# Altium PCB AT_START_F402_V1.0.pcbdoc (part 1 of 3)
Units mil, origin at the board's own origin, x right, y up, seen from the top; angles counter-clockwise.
Board outline 15424.54 x 3536.36 mil, 2 copper layers (Top Layer, Bottom Layer); 138 components, 133 nets, 522 pads, 730 vias.
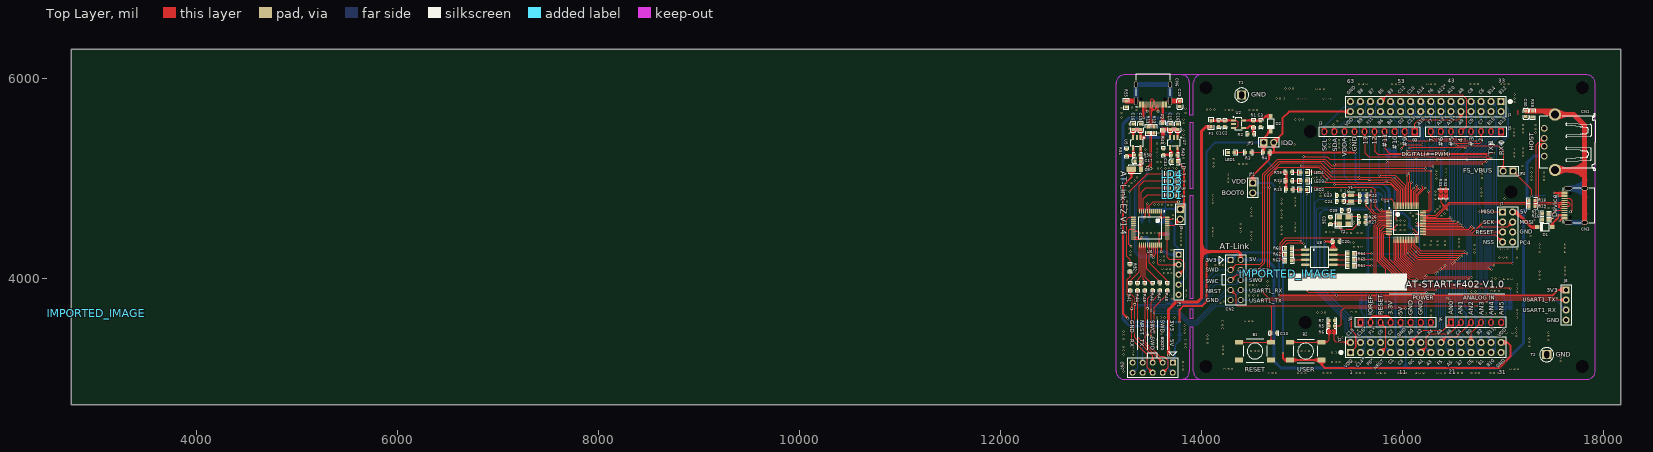
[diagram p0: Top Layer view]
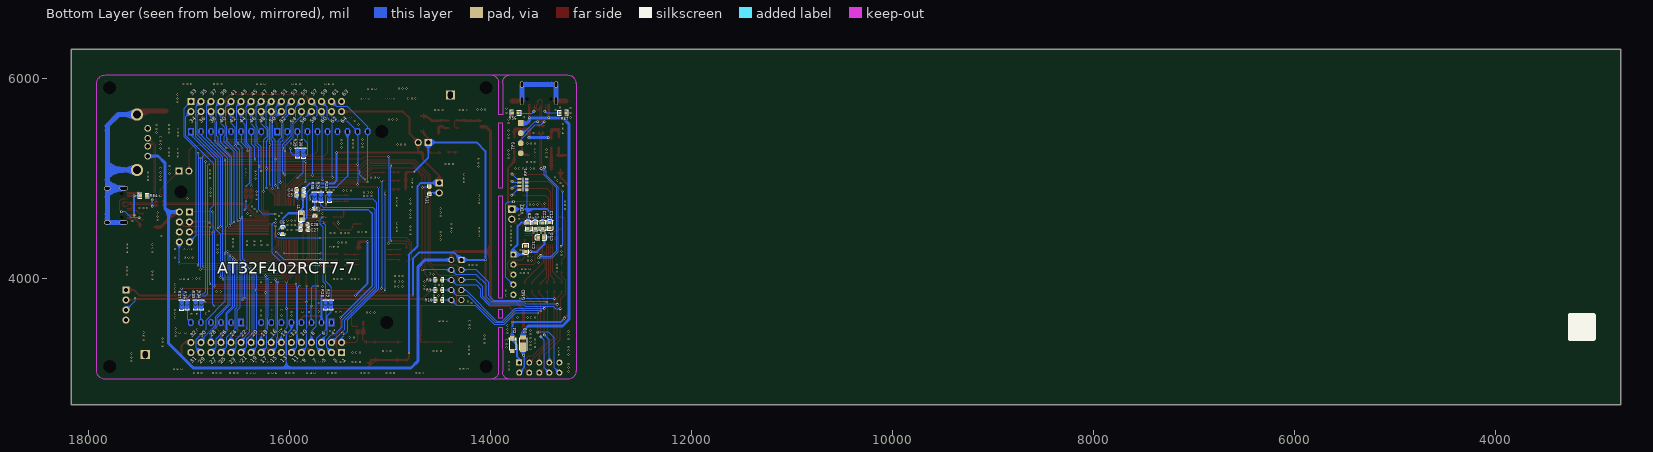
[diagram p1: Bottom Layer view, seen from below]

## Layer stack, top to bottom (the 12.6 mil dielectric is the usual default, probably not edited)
Top Layer: signal copper (thickness not stored)
Dielectric: dielectric 12.6, FR-4, Dk 4.8
Bottom Layer: signal copper (thickness not stored)

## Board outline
18174.54,2750 2750,2750 2750,6286.36 18174.54,6286.36
cut-out: 17855.2,5903.56 ccw(c17792.21,5903.56) 17729.21,5903.56 ccw(c17792.21,5903.56)
cut-out: 17854.57,3128.57 ccw(c17791.58,3128.57) 17728.58,3128.57 ccw(c17791.58,3128.57)
cut-out: 14107.57,3128.57 ccw(c14044.58,3128.57) 13981.58,3128.57 ccw(c14044.58,3128.57)
cut-out: 14107.57,5903.56 ccw(c14044.58,5903.56) 13981.58,5903.56 ccw(c14044.58,5903.56)
cut-out: 17146.57,4866.56 ccw(c17083.58,4866.56) 17020.58,4866.56 ccw(c17083.58,4866.56)
cut-out: 15096.57,3566.57 ccw(c15033.58,3566.57) 14970.58,3566.57 ccw(c15033.58,3566.57)
cut-out: 15146.57,5466.56 ccw(c15083.58,5466.56) 15020.58,5466.56 ccw(c15083.58,5466.56)

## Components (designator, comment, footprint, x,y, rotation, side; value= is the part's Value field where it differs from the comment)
B1 "BUTTON_SMT,6.0x6.0x4.5mm" BUTTON_SMT_6*6*5 14533.58,3281.57 r0 top
B2 "BUTTON_SMT,6.0x6.0x4.5mm" BUTTON_SMT_6*6*5 15038.58,3281.57 r180 top
C1 "10uF" 0603_C-M 14172.58,5545.37 r90 top
C2 "0.1uF" 0603_C-M 14232.58,5545.37 r90 top
C3 "10uF" 0603_C-M 14590.58,5545.37 r90 top
C4 "4.7uF" 0603_C-M 15896.58,4884.56 r180 bottom
C5 "0.1uF" 0603_C-M 15897.08,4834.56 r180 bottom
C6 "0.1uF" 0603_C-M 16069.58,4481.56 r90 bottom
C7 "0.1uF" 0603_C-M 15750.58,4663.56 r90 bottom
C8 "4.7uF" C0603 13556.58,4528.56 r270 bottom
C9 "CC0603KRX7R9BB104" C0603 13628.58,4528.56 r270 bottom
C10 "CC0603KRX7R9BB104" C0603 13498.58,4412.56 r0 bottom
C11 "CC0603KRX7R9BB104" C0603 13650.58,4300.56 r90 bottom
C12 "CC0603KRX7R9BB104" C0603 13410.58,4534.56 r270 bottom
C13 "0.1uF" 0603_C-M 14720.58,3460.57 r0 top
C14 "CL10A106KP8NNNC" C0603 13736.58,5165.56 r180 top
C15 "CL10A106KP8NNNC" C0603 13689.58,5515.56 r90 top
C16 "CC0603KRX7R9BB104" C0603 13764.58,5515.12 r90 top
C17 "CL10A106KP8NNNC" C0603 13367.58,5173.56 r180 top
C18 "CL10A106KP8NNNC" C0603 13319.58,5514.56 r90 top
C19 "CC0603KRX7R9BB104" C0603 13395.58,5514.12 r90 top
C20 "0.1uF" 0603_C-M 15341.08,4371.56 r0 top
C22 "CC0603KRX7R9BB104" C0603 13480.58,4530.56 r270 bottom
C23 "18pF" 0603_C-M 15383.58,4832.56 r180 top
C24 "18pF" 0603_C-M 15383.58,4773.56 r180 top
C25 "15pF" 0603_C-M 15433.08,4684.56 r180 top
C26 "15pF" 0603_C-M 15283.58,4577.06 r90 top
C27 "1uF" 0603_C-M 15857.08,4488.56 r180 bottom
C28 "0.1uF" 0603_C-M 15857.08,4537.56 r180 bottom
C29 "CC0603KRX7R9BB104" C0603 13784.58,5743.56 r90 top
C30 "CC0603KRX7R9BB104" C0603 17229.58,5643.01 r90 top
CN1 "USB type A" USB-A-TH__USB-AF-90 17466.58,5360.56 r90 top
CN2 "NC(Header 2x5)" HDR2X5#1 14290.92,4189.85 r270 top
CN3 "TYPEC-304-BCP16" USB-C-SMD_TYPEC-304-BCP16#1 17715.58,4731.56 r90 top
CN6 "TYPEC-304-BCP16" USB-C-SMD_TYPEC-304-BCP16#2 13518.58,5835.56 r180 top
CN7 "CON1" HDR2X5#2 13715.38,3166.97 r180 top
D1 "DFLS130L-7" SOD-123 17417.58,4515.56 r0 top
D2 "DFLS130L-7" SOD-123 14690.58,5545.36 r90 top
D3 "DFLS130L-7" POWERDI-123_L2.8-W1.8-LS3.7-RD 13676.62,3368.57 r90 bottom
D4 "SMF3.3A" SOD-123_L2.8-W1.8-LS3.7-RD 13782.58,3348.57 r270 bottom
D5 "DFLS130L-7" POWERDI-123_L2.8-W1.8-LS3.7-RD 13350.58,5091.56 r0 top
F1 "SMD0603B050TF" R0603#1 14096.58,5514.86 r90 top
F2 "SMD0603B050TF" R0603#2 13616.58,5518.56 r270 top
IMPORTED_IMAGE "IMPORTED_IMAGE" IMPORTED_IMAGE 3000,3659.57 r0 top
IMPORTED_IMAGE "IMPORTED_IMAGE" IMPORTED_IMAGE 14864.58,4052.57 r0 top
J1 "Header 2x16" HDR-M-2.54_2X16 16233.44,5715.86 r180 top
J2 "Header 2x16" HDR-M-2.54_2X16 16233.88,3318.14 r0 top
J3 "CON10" "FEMALE HEADER 1X10" 16123.87,5466.56 r180 top
J4 "CON8" "FEMALE HEADER 1X8" 15583.87,3566.56 r0 top
J5 "CON8" "FEMALE HEADER 1X8" 16983.87,5466.56 r180 top
J6 "CON6" "FEMALE HEADER 1X6" 16483.87,3566.57 r0 top
J7 "Header 4X2" HDR2X4 16998.88,4667.16 r270 top
J8 "Header 1x4" HDR1X4 17630.74,3890.57 r270 top
J9 "1X2P,Male,DIP_2.54" HDR1X2 13789.38,4693.97 r270 top
JP1 "NC(Header 1x2)" "HEADER 1X2" 14511.58,4956.56 r270 top
JP2 "NC(Header 1x2)" "HEADER 1X2" 17103.58,5073.56 r180 top
JP3 "NC(Header 1x2)" "HEADER 1X2" 14620.58,5358.56 r0 top
L1 "0.5A,600R@100Mhz" 0603_L 15884.58,4623.56 r270 bottom
LD1 "RED" LED0603 13742.58,4833.77 r180 top
LD2 "GREEN" LED0603 13742.58,4903.37 r180 top
LD3 "BLUE" LED0603 13742.58,4972.97 r180 top
LD4 "YELLOW" LED0603 13742.58,5042.56 r180 top
LED1 "RED" LED0603 14328.58,5259.56 r180 top
LED2 "RED" LED0603 14988.58,4890.56 r0 top
LED3 "YELLOW" LED0603 14988.58,4976.56 r0 top
LED4 "GREEN" LED0603 14988.58,5060.56 r0 top
P1 "HDR-M-2.54_1x5" HDR-M-2.54_1X5 13772.58,4042.57 r270 top
R1 "51k" 0603_R-M 14518.58,5545.37 r270 top
R2 "15k" 0603_R-M 14490.58,5444.56 r180 top
R3 "1K" 0603_R-M 14466.58,5259.56 r0 top
R4 "0R" 0603_R-M 14647.58,5258.56 r0 top
R5 "0R" 0603_R-M 15296.58,3530.57 r0 top
R6 "NC" SB-PAD 15296.58,3474.57 r0 top
R7 "100K" 0603_R-M 15296.58,3586.57 r180 top
R8 "470R" 0603_R-M 14518.27,3990.76 r0 bottom
R9 "470R" 0603_R-M 14518.27,3888.76 r0 bottom
R10 "470R" 0603_R-M 14518.27,3790.76 r0 bottom
R11 "0603WAF0000T5E" R0603#2 13469.58,5485.9 r270 top
R12 "0603WAF0000T5E" R0603#2 13528.58,5485.56 r270 top
R13 "1K" 0603_R-M 14872.58,4890.56 r0 top
R14 "1K" 0603_R-M 14871.19,4976.21 r0 top
R15 "1K" 0603_R-M 14871.19,5062.21 r0 top
R16 "0603WAF5101T5E" R0603#2 17423.58,4589.56 r180 top
R17 "0603WAF5101T5E" R0603#2 17422.58,4649.56 r180 top
R18 "0603WAF220JT5E" R0603#2 17291.92,4780.56 r0 top
R19 "0603WAF220JT5E" R0603#2 17291.58,4721.56 r0 top
R22 "0R" 0603_R-M 15609.58,4832.56 r0 top
R23 "0R" 0603_R-M 15611.58,4774.56 r0 top
R24 "NC" SB-PAD 15689.58,4815.56 r270 bottom
R25 "NC" SB-PAD 15605.58,4815.56 r270 bottom
R26 "0R" 0603_R-M 15600.58,4616.56 r0 top
R27 "0R" 0603_R-M 15600.58,4562.56 r0 top
R28 "NC" SB-PAD 15643.58,3742.57 r270 bottom
R29 "NC" SB-PAD 15589.58,3743.57 r270 bottom
R31 "10K" 0603_R-M 14610.58,4883.56 r270 bottom
R32 "NC" SB-PAD 16433.58,4848.44 r270 top
R33 "NC" SB-PAD 16380.58,4848.85 r270 top
R34 "0R" SB-PAD 16880.58,3742.45 r270 bottom
R35 "NC" SB-PAD 16936.58,3741.96 r270 bottom
R36 "NC" SB-PAD 17020.58,3741.45 r270 bottom
R37 "0R" SB-PAD 17076.58,3740.84 r270 bottom
R38 "NC" SB-PAD 15864.58,5253.93 r270 bottom
R39 "0R" SB-PAD 15924.58,5254.56 r270 bottom
R41 "33R" 0603_R-M 13290.58,3920.57 r270 top
R43 "47K" 0603_R-M 13730.42,5236.02 r180 top
R44 "33R" 0603_R-M 13364.58,3920.57 r270 top
R45 "33R" 0603_R-M 13436.58,3920.57 r270 top
R46 "33R" 0603_R-M 13514.58,3922.57 r270 top
R47 "33R" 0603_R-M 13586.58,3924.57 r270 top
R48 "33R" 0603_R-M 13660.58,3920.57 r270 top
R49 "15K" 0603_R-M 13620.58,5264.56 r270 top
R50 "51K" 0603_R-M 13362.58,5233.56 r180 top
R51 "15K" 0603_R-M 13254.58,5258.56 r270 top
R52 "33R" 0603_R-M 13288.58,4110.56 r270 top
R54 "0603WAF1002T5E" R0603#2 17455.92,4827.56 r0 bottom
R55 "RC0603FR-071ML" R0603#2 13250.58,5741.9 r270 top
R56 "0603WAF5101T5E" R0603#2 13755.58,5651.56 r0 bottom
R57 "0603WAF5101T5E" R0603#2 13279.58,5651.56 r180 bottom
R58 "0R" SB-PAD 15750.58,4817.56 r270 bottom
R59 "RC0603FR-071ML" R0603#2 17296.58,5641.9 r270 top
R60 "0603WAF330JT5E" R0603#2 14866.58,4300.56 r0 top
R61 "0603WAF330JT5E" R0603#2 15486.24,4131.56 r180 top
R62 "0603WAF330JT5E" R0603#2 14866.92,4241.56 r0 top
R63 "0603WAF330JT5E" R0603#2 14867.58,4181.56 r0 top
R64 "0603WAF330JT5E" R0603#2 15486.92,4251.56 r180 top
R65 "0603WAF330JT5E" R0603#2 15486.92,4191.56 r180 top
RP1 "1K" 0603*4,8P4R 13640.58,4887.56 r90 bottom
T1 "Testpoint" TESTHOOK 14400.58,5830.56 r270 top
T2 "Testpoint" TESTHOOK 17437.58,3246.57 r90 top
TP3 "1X4P_2.54F" "HDR1X4 - TOP" 13699.93,5551.02 r90 bottom
U2 "RT9080N-08GJ5" SOT-23-5 14382.58,5477.54 r0 top
U4 "AT32F402RCT7-7" IC_LQFP64_7X7 16037.58,4559.56 r0 top
U5 "RT9080N-08GJ5" SOT-23-5 13295.14,5340.91 r270 top
U6 "AT32F403CGT6" "LQFP48 - 2" 13600.09,4673.02 r270 top
U7 "RT9080N-08GJ5" SOT-23-5 13664.35,5342.91 r270 top
U8 "EN25QH128A-104HIP2T" SOP-8_L5.3-W5.3-P1.27-LS8.0-BL 15174.58,4216.56 r270 top
Y1 "32.768KHz" "XTAL_SOP - FC-12M" 15487.58,4832.56 r270 top
Y2 "CJ13-120001210B20" CRYSTAL-SMD_4P-L3.2-W2.5-BL 15416.58,4583.56 r0 top

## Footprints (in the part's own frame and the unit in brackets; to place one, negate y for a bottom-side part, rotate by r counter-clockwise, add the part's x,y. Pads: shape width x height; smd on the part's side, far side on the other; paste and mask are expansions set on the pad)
0603*4,8P4R [mm]
  rect 0.55x0.95 smd paste+0 mask+0.102: 1(0,0) 4(2.7,0) 5(2.7,1.85) 8(0,1.85)
  rect 0.5x0.95 smd paste+0 mask+0.102: 2(0.9,0) 3(1.8,0) 6(1.8,1.85) 7(0.9,1.85)
  silkscreen extent -0.43,0.94 3.1,0.94
0603_C-M [mil]
  rect 30x30 smd paste+0 mask+4: 1(27.5,0) 2(-27.5,0)
  silkscreen extent -50,-21 50,21
0603_L [mm]
  rect 0.93x0.9 smd paste+0 mask+0.102: 1(-0.77,0) 2(0.77,0)
  silkscreen extent -1.4,-0.64 1.4,0.64
0603_R-M [mil]
  rect 30x30 smd paste+0 mask+4: 1(27.5,0) 2(-27.5,0)
  silkscreen extent -50,-21 50,21
BUTTON_SMT_6*6*5 [mm]
  rect 2x1.2 smd paste+0 mask+0.102: 1(-4,2.25) 2(4,2.25) 3(-4,-2.25) 4(4,-2.25)
  silkscreen extent -3,-3 3,3
C0603 [mm]
  rect 0.8x0.9 smd paste+0 mask+0.051: 1(-0.7,0) 2(0.7,0)
  silkscreen extent -1.41,-0.71 1.39,0.72
CRYSTAL-SMD_4P-L3.2-W2.5-BL [mm]
  rect 1.4x1.2 smd paste+0 mask+0.051: 1(-1.1,-0.85) 2(1.1,-0.85) 3(1.1,0.85) 4(-1.1,0.85)
  silkscreen extent -2.26,-1.91 2.03,1.68
"FEMALE HEADER 1X6" [mm]
  oval 1x0.7 hole 0.7 slot 1 at 90 deg: 1(0,0) 2(2.54,0) 3(5.08,0) 4(7.62,0) 5(10.16,0) 6(12.7,0)
  Top Layer region: 13.4,-0.2 13.306,-0.55 13.05,-0.806 12.7,-0.9 12.35,-0.806 12.094,-0.55 12,-0.2 12,0.2 12.094,0.55 12.35,0.806 12.7,0.9 13.05,0.806 13.306,0.55 13.4,0.2
  Top Layer region: 10.86,-0.2 10.766,-0.55 10.51,-0.806 10.16,-0.9 9.81,-0.806 9.554,-0.55 9.46,-0.2 9.46,0.2 9.554,0.55 9.81,0.806 10.16,0.9 10.51,0.806 10.766,0.55 10.86,0.2
  Top Layer region: 8.32,-0.2 8.226,-0.55 7.97,-0.806 7.62,-0.9 7.27,-0.806 7.014,-0.55 6.92,-0.2 6.92,0.2 7.014,0.55 7.27,0.806 7.62,0.9 7.97,0.806 8.226,0.55 8.32,0.2
  Top Layer region: 5.78,-0.2 5.686,-0.55 5.43,-0.806 5.08,-0.9 4.73,-0.806 4.474,-0.55 4.38,-0.2 4.38,0.2 4.474,0.55 4.73,0.806 5.08,0.9 5.43,0.806 5.686,0.55 5.78,0.2
  Top Layer region: 3.24,-0.2 3.146,-0.55 2.89,-0.806 2.54,-0.9 2.19,-0.806 1.934,-0.55 1.84,-0.2 1.84,0.2 1.934,0.55 2.19,0.806 2.54,0.9 2.89,0.806 3.146,0.55 3.24,0.2
  Top Layer region: -0.7,0.9 0.7,0.9 0.7,-0.9 -0.7,-0.9
  Bottom Layer region: 13.4,-0.2 13.306,-0.55 13.05,-0.806 12.7,-0.9 12.35,-0.806 12.094,-0.55 12,-0.2 12,0.2 12.094,0.55 12.35,0.806 12.7,0.9 13.05,0.806 13.306,0.55 13.4,0.2
  Bottom Layer region: 10.86,-0.2 10.766,-0.55 10.51,-0.806 10.16,-0.9 9.81,-0.806 9.554,-0.55 9.46,-0.2 9.46,0.2 9.554,0.55 9.81,0.806 10.16,0.9 10.51,0.806 10.766,0.55 10.86,0.2
  Bottom Layer region: 8.32,-0.2 8.226,-0.55 7.97,-0.806 7.62,-0.9 7.27,-0.806 7.014,-0.55 6.92,-0.2 6.92,0.2 7.014,0.55 7.27,0.806 7.62,0.9 7.97,0.806 8.226,0.55 8.32,0.2
  Bottom Layer region: 5.78,-0.2 5.686,-0.55 5.43,-0.806 5.08,-0.9 4.73,-0.806 4.474,-0.55 4.38,-0.2 4.38,0.2 4.474,0.55 4.73,0.806 5.08,0.9 5.43,0.806 5.686,0.55 5.78,0.2
  Bottom Layer region: 3.24,-0.2 3.146,-0.55 2.89,-0.806 2.54,-0.9 2.19,-0.806 1.934,-0.55 1.84,-0.2 1.84,0.2 1.934,0.55 2.19,0.806 2.54,0.9 2.89,0.806 3.146,0.55 3.24,0.2
  Bottom Layer region: -0.7,0.9 0.7,0.9 0.7,-0.9 -0.7,-0.9
  Multi-Layer region: 13.4,-0.2 13.306,-0.55 13.05,-0.806 12.7,-0.9 12.35,-0.806 12.094,-0.55 12,-0.2 12,0.2 12.094,0.55 12.35,0.806 12.7,0.9 13.05,0.806 13.306,0.55 13.4,0.2
  Multi-Layer region: 10.86,-0.2 10.766,-0.55 10.51,-0.806 10.16,-0.9 9.81,-0.806 9.554,-0.55 9.46,-0.2 9.46,0.2 9.554,0.55 9.81,0.806 10.16,0.9 10.51,0.806 10.766,0.55 10.86,0.2
  Multi-Layer region: 8.32,-0.2 8.226,-0.55 7.97,-0.806 7.62,-0.9 7.27,-0.806 7.014,-0.55 6.92,-0.2 6.92,0.2 7.014,0.55 7.27,0.806 7.62,0.9 7.97,0.806 8.226,0.55 8.32,0.2
  Multi-Layer region: 5.78,-0.2 5.686,-0.55 5.43,-0.806 5.08,-0.9 4.73,-0.806 4.474,-0.55 4.38,-0.2 4.38,0.2 4.474,0.55 4.73,0.806 5.08,0.9 5.43,0.806 5.686,0.55 5.78,0.2
  Multi-Layer region: 3.24,-0.2 3.146,-0.55 2.89,-0.806 2.54,-0.9 2.19,-0.806 1.934,-0.55 1.84,-0.2 1.84,0.2 1.934,0.55 2.19,0.806 2.54,0.9 2.89,0.806 3.146,0.55 3.24,0.2
  Multi-Layer region: -0.7,0.9 0.7,0.9 0.7,-0.9 -0.7,-0.9
  silkscreen extent -1.27,-1.17 13.97,1.27
"FEMALE HEADER 1X8" [mm]
  oval 1x0.7 hole 0.7 slot 1 at 90 deg: 1(0,0) 2(2.54,0) 3(5.08,0) 4(7.62,0) 5(10.16,0) 6(12.7,0) 7(15.24,0) 8(17.78,0)
  Top Layer region: -0.7,0.9 0.7,0.9 0.7,-0.9 -0.7,-0.9
  Top Layer region: 3.24,-0.2 3.146,-0.55 2.89,-0.806 2.54,-0.9 2.19,-0.806 1.934,-0.55 1.84,-0.2 1.84,0.2 1.934,0.55 2.19,0.806 2.54,0.9 2.89,0.806 3.146,0.55 3.24,0.2
  Top Layer region: 5.78,-0.2 5.686,-0.55 5.43,-0.806 5.08,-0.9 4.73,-0.806 4.474,-0.55 4.38,-0.2 4.38,0.2 4.474,0.55 4.73,0.806 5.08,0.9 5.43,0.806 5.686,0.55 5.78,0.2
  Top Layer region: 8.32,-0.2 8.226,-0.55 7.97,-0.806 7.62,-0.9 7.27,-0.806 7.014,-0.55 6.92,-0.2 6.92,0.2 7.014,0.55 7.27,0.806 7.62,0.9 7.97,0.806 8.226,0.55 8.32,0.2
  Top Layer region: 10.86,-0.2 10.766,-0.55 10.51,-0.806 10.16,-0.9 9.81,-0.806 9.554,-0.55 9.46,-0.2 9.46,0.2 9.554,0.55 9.81,0.806 10.16,0.9 10.51,0.806 10.766,0.55 10.86,0.2
  Top Layer region: 13.4,-0.2 13.306,-0.55 13.05,-0.806 12.7,-0.9 12.35,-0.806 12.094,-0.55 12,-0.2 12,0.2 12.094,0.55 12.35,0.806 12.7,0.9 13.05,0.806 13.306,0.55 13.4,0.2
  Top Layer region: 15.94,-0.2 15.846,-0.55 15.59,-0.806 15.24,-0.9 14.89,-0.806 14.634,-0.55 14.54,-0.2 14.54,0.2 14.634,0.55 14.89,0.806 15.24,0.9 15.59,0.806 15.846,0.55 15.94,0.2
  Top Layer region: 18.48,-0.2 18.386,-0.55 18.13,-0.806 17.78,-0.9 17.43,-0.806 17.174,-0.55 17.08,-0.2 17.08,0.2 17.174,0.55 17.43,0.806 17.78,0.9 18.13,0.806 18.386,0.55 18.48,0.2
  Bottom Layer region: -0.7,0.9 0.7,0.9 0.7,-0.9 -0.7,-0.9
  Bottom Layer region: 3.24,-0.2 3.146,-0.55 2.89,-0.806 2.54,-0.9 2.19,-0.806 1.934,-0.55 1.84,-0.2 1.84,0.2 1.934,0.55 2.19,0.806 2.54,0.9 2.89,0.806 3.146,0.55 3.24,0.2
  Bottom Layer region: 5.78,-0.2 5.686,-0.55 5.43,-0.806 5.08,-0.9 4.73,-0.806 4.474,-0.55 4.38,-0.2 4.38,0.2 4.474,0.55 4.73,0.806 5.08,0.9 5.43,0.806 5.686,0.55 5.78,0.2
  Bottom Layer region: 8.32,-0.2 8.226,-0.55 7.97,-0.806 7.62,-0.9 7.27,-0.806 7.014,-0.55 6.92,-0.2 6.92,0.2 7.014,0.55 7.27,0.806 7.62,0.9 7.97,0.806 8.226,0.55 8.32,0.2
  Bottom Layer region: 10.86,-0.2 10.766,-0.55 10.51,-0.806 10.16,-0.9 9.81,-0.806 9.554,-0.55 9.46,-0.2 9.46,0.2 9.554,0.55 9.81,0.806 10.16,0.9 10.51,0.806 10.766,0.55 10.86,0.2
  Bottom Layer region: 13.4,-0.2 13.306,-0.55 13.05,-0.806 12.7,-0.9 12.35,-0.806 12.094,-0.55 12,-0.2 12,0.2 12.094,0.55 12.35,0.806 12.7,0.9 13.05,0.806 13.306,0.55 13.4,0.2
  Bottom Layer region: 15.94,-0.2 15.846,-0.55 15.59,-0.806 15.24,-0.9 14.89,-0.806 14.634,-0.55 14.54,-0.2 14.54,0.2 14.634,0.55 14.89,0.806 15.24,0.9 15.59,0.806 15.846,0.55 15.94,0.2
  Bottom Layer region: 18.48,-0.2 18.386,-0.55 18.13,-0.806 17.78,-0.9 17.43,-0.806 17.174,-0.55 17.08,-0.2 17.08,0.2 17.174,0.55 17.43,0.806 17.78,0.9 18.13,0.806 18.386,0.55 18.48,0.2
  Multi-Layer region: -0.7,0.9 0.7,0.9 0.7,-0.9 -0.7,-0.9
  Multi-Layer region: 3.24,-0.2 3.146,-0.55 2.89,-0.806 2.54,-0.9 2.19,-0.806 1.934,-0.55 1.84,-0.2 1.84,0.2 1.934,0.55 2.19,0.806 2.54,0.9 2.89,0.806 3.146,0.55 3.24,0.2
  Multi-Layer region: 5.78,-0.2 5.686,-0.55 5.43,-0.806 5.08,-0.9 4.73,-0.806 4.474,-0.55 4.38,-0.2 4.38,0.2 4.474,0.55 4.73,0.806 5.08,0.9 5.43,0.806 5.686,0.55 5.78,0.2
  Multi-Layer region: 8.32,-0.2 8.226,-0.55 7.97,-0.806 7.62,-0.9 7.27,-0.806 7.014,-0.55 6.92,-0.2 6.92,0.2 7.014,0.55 7.27,0.806 7.62,0.9 7.97,0.806 8.226,0.55 8.32,0.2
  Multi-Layer region: 10.86,-0.2 10.766,-0.55 10.51,-0.806 10.16,-0.9 9.81,-0.806 9.554,-0.55 9.46,-0.2 9.46,0.2 9.554,0.55 9.81,0.806 10.16,0.9 10.51,0.806 10.766,0.55 10.86,0.2
  Multi-Layer region: 13.4,-0.2 13.306,-0.55 13.05,-0.806 12.7,-0.9 12.35,-0.806 12.094,-0.55 12,-0.2 12,0.2 12.094,0.55 12.35,0.806 12.7,0.9 13.05,0.806 13.306,0.55 13.4,0.2
  Multi-Layer region: 15.94,-0.2 15.846,-0.55 15.59,-0.806 15.24,-0.9 14.89,-0.806 14.634,-0.55 14.54,-0.2 14.54,0.2 14.634,0.55 14.89,0.806 15.24,0.9 15.59,0.806 15.846,0.55 15.94,0.2
  Multi-Layer region: 18.48,-0.2 18.386,-0.55 18.13,-0.806 17.78,-0.9 17.43,-0.806 17.174,-0.55 17.08,-0.2 17.08,0.2 17.174,0.55 17.43,0.806 17.78,0.9 18.13,0.806 18.386,0.55 18.48,0.2
  silkscreen extent -1.27,-1.17 19.05,1.27
"FEMALE HEADER 1X10" [mm]
  oval 1x0.7 hole 0.7 slot 1 at 90 deg: 1(0,0) 2(2.54,0) 3(5.08,0) 4(7.62,0) 5(10.16,0) 6(12.7,0) 7(15.24,0) 8(17.78,0) 9(20.32,0) 10(22.86,0)
  Top Layer region: 23.56,-0.2 23.466,-0.55 23.21,-0.806 22.86,-0.9 22.51,-0.806 22.254,-0.55 22.16,-0.2 22.16,0.2 22.254,0.55 22.51,0.806 22.86,0.9 23.21,0.806 23.466,0.55 23.56,0.2
  Top Layer region: 21.02,-0.2 20.926,-0.55 20.67,-0.806 20.32,-0.9 19.97,-0.806 19.714,-0.55 19.62,-0.2 19.62,0.2 19.714,0.55 19.97,0.806 20.32,0.9 20.67,0.806 20.926,0.55 21.02,0.2
  Top Layer region: 18.48,-0.2 18.386,-0.55 18.13,-0.806 17.78,-0.9 17.43,-0.806 17.174,-0.55 17.08,-0.2 17.08,0.2 17.174,0.55 17.43,0.806 17.78,0.9 18.13,0.806 18.386,0.55 18.48,0.2
  Top Layer region: 15.94,-0.2 15.846,-0.55 15.59,-0.806 15.24,-0.9 14.89,-0.806 14.634,-0.55 14.54,-0.2 14.54,0.2 14.634,0.55 14.89,0.806 15.24,0.9 15.59,0.806 15.846,0.55 15.94,0.2
  Top Layer region: 13.4,-0.2 13.306,-0.55 13.05,-0.806 12.7,-0.9 12.35,-0.806 12.094,-0.55 12,-0.2 12,0.2 12.094,0.55 12.35,0.806 12.7,0.9 13.05,0.806 13.306,0.55 13.4,0.2
  Top Layer region: 10.86,-0.2 10.766,-0.55 10.51,-0.806 10.16,-0.9 9.81,-0.806 9.554,-0.55 9.46,-0.2 9.46,0.2 9.554,0.55 9.81,0.806 10.16,0.9 10.51,0.806 10.766,0.55 10.86,0.2
  Top Layer region: 8.32,-0.2 8.226,-0.55 7.97,-0.806 7.62,-0.9 7.27,-0.806 7.014,-0.55 6.92,-0.2 6.92,0.2 7.014,0.55 7.27,0.806 7.62,0.9 7.97,0.806 8.226,0.55 8.32,0.2
  Top Layer region: 5.78,-0.2 5.686,-0.55 5.43,-0.806 5.08,-0.9 4.73,-0.806 4.474,-0.55 4.38,-0.2 4.38,0.2 4.474,0.55 4.73,0.806 5.08,0.9 5.43,0.806 5.686,0.55 5.78,0.2
  Top Layer region: 3.24,-0.2 3.146,-0.55 2.89,-0.806 2.54,-0.9 2.19,-0.806 1.934,-0.55 1.84,-0.2 1.84,0.2 1.934,0.55 2.19,0.806 2.54,0.9 2.89,0.806 3.146,0.55 3.24,0.2
  Top Layer region: -0.7,0.9 0.7,0.9 0.7,-0.9 -0.7,-0.9
  Bottom Layer region: 23.56,-0.2 23.466,-0.55 23.21,-0.806 22.86,-0.9 22.51,-0.806 22.254,-0.55 22.16,-0.2 22.16,0.2 22.254,0.55 22.51,0.806 22.86,0.9 23.21,0.806 23.466,0.55 23.56,0.2
  Bottom Layer region: 21.02,-0.2 20.926,-0.55 20.67,-0.806 20.32,-0.9 19.97,-0.806 19.714,-0.55 19.62,-0.2 19.62,0.2 19.714,0.55 19.97,0.806 20.32,0.9 20.67,0.806 20.926,0.55 21.02,0.2
  Bottom Layer region: 18.48,-0.2 18.386,-0.55 18.13,-0.806 17.78,-0.9 17.43,-0.806 17.174,-0.55 17.08,-0.2 17.08,0.2 17.174,0.55 17.43,0.806 17.78,0.9 18.13,0.806 18.386,0.55 18.48,0.2
  Bottom Layer region: 15.94,-0.2 15.846,-0.55 15.59,-0.806 15.24,-0.9 14.89,-0.806 14.634,-0.55 14.54,-0.2 14.54,0.2 14.634,0.55 14.89,0.806 15.24,0.9 15.59,0.806 15.846,0.55 15.94,0.2
  Bottom Layer region: 13.4,-0.2 13.306,-0.55 13.05,-0.806 12.7,-0.9 12.35,-0.806 12.094,-0.55 12,-0.2 12,0.2 12.094,0.55 12.35,0.806 12.7,0.9 13.05,0.806 13.306,0.55 13.4,0.2
  Bottom Layer region: 10.86,-0.2 10.766,-0.55 10.51,-0.806 10.16,-0.9 9.81,-0.806 9.554,-0.55 9.46,-0.2 9.46,0.2 9.554,0.55 9.81,0.806 10.16,0.9 10.51,0.806 10.766,0.55 10.86,0.2
  Bottom Layer region: 8.32,-0.2 8.226,-0.55 7.97,-0.806 7.62,-0.9 7.27,-0.806 7.014,-0.55 6.92,-0.2 6.92,0.2 7.014,0.55 7.27,0.806 7.62,0.9 7.97,0.806 8.226,0.55 8.32,0.2
  Bottom Layer region: 5.78,-0.2 5.686,-0.55 5.43,-0.806 5.08,-0.9 4.73,-0.806 4.474,-0.55 4.38,-0.2 4.38,0.2 4.474,0.55 4.73,0.806 5.08,0.9 5.43,0.806 5.686,0.55 5.78,0.2
  Bottom Layer region: 3.24,-0.2 3.146,-0.55 2.89,-0.806 2.54,-0.9 2.19,-0.806 1.934,-0.55 1.84,-0.2 1.84,0.2 1.934,0.55 2.19,0.806 2.54,0.9 2.89,0.806 3.146,0.55 3.24,0.2
  Bottom Layer region: -0.7,0.9 0.7,0.9 0.7,-0.9 -0.7,-0.9
  Multi-Layer region: 23.56,-0.2 23.466,-0.55 23.21,-0.806 22.86,-0.9 22.51,-0.806 22.254,-0.55 22.16,-0.2 22.16,0.2 22.254,0.55 22.51,0.806 22.86,0.9 23.21,0.806 23.466,0.55 23.56,0.2
  Multi-Layer region: 21.02,-0.2 20.926,-0.55 20.67,-0.806 20.32,-0.9 19.97,-0.806 19.714,-0.55 19.62,-0.2 19.62,0.2 19.714,0.55 19.97,0.806 20.32,0.9 20.67,0.806 20.926,0.55 21.02,0.2
  Multi-Layer region: 18.48,-0.2 18.386,-0.55 18.13,-0.806 17.78,-0.9 17.43,-0.806 17.174,-0.55 17.08,-0.2 17.08,0.2 17.174,0.55 17.43,0.806 17.78,0.9 18.13,0.806 18.386,0.55 18.48,0.2
  Multi-Layer region: 15.94,-0.2 15.846,-0.55 15.59,-0.806 15.24,-0.9 14.89,-0.806 14.634,-0.55 14.54,-0.2 14.54,0.2 14.634,0.55 14.89,0.806 15.24,0.9 15.59,0.806 15.846,0.55 15.94,0.2
  Multi-Layer region: 13.4,-0.2 13.306,-0.55 13.05,-0.806 12.7,-0.9 12.35,-0.806 12.094,-0.55 12,-0.2 12,0.2 12.094,0.55 12.35,0.806 12.7,0.9 13.05,0.806 13.306,0.55 13.4,0.2
  Multi-Layer region: 10.86,-0.2 10.766,-0.55 10.51,-0.806 10.16,-0.9 9.81,-0.806 9.554,-0.55 9.46,-0.2 9.46,0.2 9.554,0.55 9.81,0.806 10.16,0.9 10.51,0.806 10.766,0.55 10.86,0.2
  Multi-Layer region: 8.32,-0.2 8.226,-0.55 7.97,-0.806 7.62,-0.9 7.27,-0.806 7.014,-0.55 6.92,-0.2 6.92,0.2 7.014,0.55 7.27,0.806 7.62,0.9 7.97,0.806 8.226,0.55 8.32,0.2
  Multi-Layer region: 5.78,-0.2 5.686,-0.55 5.43,-0.806 5.08,-0.9 4.73,-0.806 4.474,-0.55 4.38,-0.2 4.38,0.2 4.474,0.55 4.73,0.806 5.08,0.9 5.43,0.806 5.686,0.55 5.78,0.2
  Multi-Layer region: 3.24,-0.2 3.146,-0.55 2.89,-0.806 2.54,-0.9 2.19,-0.806 1.934,-0.55 1.84,-0.2 1.84,0.2 1.934,0.55 2.19,0.806 2.54,0.9 2.89,0.806 3.146,0.55 3.24,0.2
  Multi-Layer region: -0.7,0.9 0.7,0.9 0.7,-0.9 -0.7,-0.9
  silkscreen extent -1.27,-1.17 24.1,1.27
HDR1X2 [mm]
  rect 1.8x1.8 hole 1 slot 1.005 at 0 deg paste+0 mask+0.051: 1(0,0)
  round 1.8 hole 1 slot 1.005 at 0 deg paste+0 mask+0.051: 2(2.54,0)
  silkscreen extent -1.27,-1.27 3.81,1.27
HDR1X4 [mm]
  rect 1.8x1.8 hole 1 paste+0 mask+0.102: 1(0,0)
  round 1.8 hole 1 paste+0 mask+0.102: 2(2.54,0) 3(5.08,0) 4(7.62,0)
  silkscreen extent -1.27,-1.27 8.89,1.27
"HDR1X4 - TOP" [mm]
  rect 1.5x1.5 smd paste+0 mask+0.102: 1(0,0)
  round 1.5 smd paste+0 mask+0.102: 2(-2.54,0) 3(-5.08,0) 4(-7.62,0)
HDR2X4 [mm]
  rect 1.8x1.8 hole 1 paste+0 mask+0.102: 1(0,0)
  round 1.8 hole 1 paste+0 mask+0.102: 2(0,2.54) 3(2.54,0) 4(2.54,2.54) 5(5.08,0) 6(5.08,2.54) 7(7.62,0) 8(7.62,2.54)
  silkscreen extent -1.27,-1.27 8.89,3.81
HDR2X5#1 [mm]
  rect 1.5x1.5 hole 0.9 slot 0.905 at 0 deg paste+0 mask+0.051: 1(0,0)
  round 1.5 hole 0.9 slot 0.905 at 0 deg paste+0 mask+0.051: 2(0,2.54) 3(2.54,0) 4(2.54,2.54) 5(5.08,0) 6(5.08,2.54) 7(7.62,0) 8(7.62,2.54) 9(10.16,0) 10(10.16,2.54)
  silkscreen extent -1.27,-1.27 11.43,3.81
HDR2X5#2 [mm]
  rect 1.5x1.5 hole 0.9 paste+0 mask+0.102: 1(0,0)
  round 1.5 hole 0.9 paste+0 mask+0.102: 2(0,2.54) 3(2.54,0) 4(2.54,2.54) 5(5.08,0) 6(5.08,2.54) 7(7.62,0) 8(7.62,2.54) 9(10.16,0) 10(10.16,2.54)
  silkscreen extent -1.27,-1.27 11.43,3.81
HDR-M-2.54_1X5 [mil]
  rect 62x62 hole 35 paste+0 mask+2: 1(-200,0)
  round 62 hole 35 paste+0 mask+2: 2(-100,0) 3(0,0) 4(100,0) 5(200,0)
  silkscreen extent -250,-50 250,50
HDR-M-2.54_2X16 [mm]
  rect 1.8x1.8 hole 1 paste+0 mask+0.051: 1(-19.05,-1.27)
  round 1.8 hole 1 paste+0 mask+0.051: 2(-19.05,1.27) 3(-16.51,-1.27) 4(-16.51,1.27) 5(-13.97,-1.27) 6(-13.97,1.27) 7(-11.43,-1.27) 8(-11.43,1.27) 9(-8.89,-1.27) 10(-8.89,1.27) 11(-6.35,-1.27) 12(-6.35,1.27) 13(-3.81,-1.27) 14(-3.81,1.27) 15(-1.27,-1.27) 16(-1.27,1.27) 17(1.27,-1.27) 18(1.27,1.27) 19(3.81,-1.27) 20(3.81,1.27) 21(6.35,-1.27) 22(6.35,1.27) 23(8.89,-1.27) 24(8.89,1.27) 25(11.43,-1.27) 26(11.43,1.27) 27(13.97,-1.27) 28(13.97,1.27) 29(16.51,-1.27) 30(16.51,1.27) 31(19.05,-1.27) 32(19.05,1.27)
  silkscreen extent -20.32,-2.54 20.32,2.54
"HEADER 1X2" [mm]
  rect 1.8x1.8 hole 1 slot 1.005 at 0 deg paste+0 mask+0.051: 1(0,0)
  round 1.8 hole 1 slot 1.005 at 0 deg paste+0 mask+0.051: 2(2.54,0)
  silkscreen extent -1.27,-1.27 3.81,1.27
IC_LQFP64_7X7 [mm]
  rect 1.6x0.25 smd paste+0 mask+0.102: 1(-4.3,3) 2(-4.3,2.6) 3(-4.3,2.2) 4(-4.3,1.8) 5(-4.3,1.4) 6(-4.3,1) 7(-4.3,0.6) 8(-4.3,0.2) 9(-4.3,-0.2) 10(-4.3,-0.6) 11(-4.3,-1) 12(-4.3,-1.4) 13(-4.3,-1.8) 14(-4.3,-2.2) 15(-4.3,-2.6) 16(-4.3,-3) 33(4.3,-3) 34(4.3,-2.6) 35(4.3,-2.2) 36(4.3,-1.8) 37(4.3,-1.4) 38(4.3,-1) 39(4.3,-0.6) 40(4.3,-0.2) 41(4.3,0.2) 42(4.3,0.6) 43(4.3,1) 44(4.3,1.4) 45(4.3,1.8) 46(4.3,2.2) 47(4.3,2.6) 48(4.3,3)
  rect 0.25x1.6 smd paste+0 mask+0.102: 17(-3,-4.3) 18(-2.6,-4.3) 19(-2.2,-4.3) 20(-1.8,-4.3) 21(-1.4,-4.3) 22(-1,-4.3) 23(-0.6,-4.3) 24(-0.2,-4.3) 25(0.2,-4.3) 26(0.6,-4.3) 27(1,-4.3) 28(1.4,-4.3) 29(1.8,-4.3) 30(2.2,-4.3) 31(2.6,-4.3) 32(3,-4.3) 49(3,4.3) 50(2.6,4.3) 51(2.2,4.3) 52(1.8,4.3) 53(1.4,4.3) 54(1,4.3) 55(0.6,4.3) 56(0.2,4.3) 57(-0.2,4.3) 58(-0.6,4.3) 59(-1,4.3) 60(-1.4,4.3) 61(-1.8,4.3) 62(-2.2,4.3) 63(-2.6,4.3) 64(-3,4.3)
  silkscreen extent -4.42,-3.1 3.1,3.82
IMPORTED_IMAGE [mil]
LED0603 [mil]
  rect 36x32 smd paste+0 mask+4: 1(-0.04,0.2) 2(60.96,0.2)
  silkscreen extent -28,-28 110,27
"LQFP48 - 2" [mm]
  rect 1.2x0.3 smd paste+0 mask+0.102: 1(0,0) 2(0,-0.5) 3(0,-1) 4(0,-1.5) 5(0,-2) 6(0,-2.5) 7(0,-3) 8(0,-3.5) 9(0,-4) 10(0,-4.5) 11(0,-5) 12(0,-5.5) 25(8.5,-5.5) 26(8.5,-5) 27(8.5,-4.5) 28(8.5,-4) 29(8.5,-3.5) 30(8.5,-3) 31(8.5,-2.5) 32(8.5,-2) 33(8.5,-1.5) 34(8.5,-1) 35(8.5,-0.5) 36(8.5,0)
  rect 0.3x1.2 smd paste+0 mask+0.102: 13(1.5,-7) 14(2,-7) 15(2.5,-7) 16(3,-7) 17(3.5,-7) 18(4,-7) 19(4.5,-7) 20(5,-7) 21(5.5,-7) 22(6,-7) 23(6.5,-7) 24(7,-7) 37(7,1.5) 38(6.5,1.5) 39(6,1.5) 40(5.5,1.5) 41(5,1.5) 42(4.5,1.5) 43(4,1.5) 44(3.5,1.5) 45(3,1.5) 46(2.5,1.5) 47(2,1.5) 48(1.5,1.5)
  silkscreen extent -0.12,-5.71 7.11,0.89
POWERDI-123_L2.8-W1.8-LS3.7-RD [mm]
  rect 2.4x1.5 smd paste+0 mask+0.051: 1(-1.187,0)
  rect 1.05x1.5 smd paste+0 mask+0.051: 2(1.187,0)
  silkscreen extent -2,-1 1.2,1
R0603#1 [mil]
  rect 36x32 smd paste+0 mask+4: 1(-0.04,0.2) 2(60.96,0.2)
  silkscreen extent -28,-27 89,27
R0603#2 [mil]
  rect 31.75x34.02 smd paste-3937.01 mask+2: 1(-29.66,0) 2(29.66,0)
  silkscreen extent -55,-26 55,26
SB-PAD [mil]
  Top Layer region: -47.24,-19.68 -47.24,19.68 -16.45,19.68 1,0 -17.05,-19.68
  Top Layer region: -4.69,19.68 15,0 -4.69,-19.69 47.24,-19.68 47.24,19.68
  silkscreen extent -50,-23 50,23
SOD-123 [mm]
  rect 1.2x1 smd paste+0 mask+0.102: 1(1.905,0) 2(-1.905,0)
  silkscreen extent -1.14,-0.89 1.14,0.89
SOD-123_L2.8-W1.8-LS3.7-RD [mm]
  rect 0.95x1.15 smd paste+0 mask+0.051: 1(-1.692,0) 2(1.692,0)
  silkscreen extent -1.63,-0.94 1.41,0.94
SOP-8_L5.3-W5.3-P1.27-LS8.0-BL [mil]
  oval 23.98x86.79 smd mask+2: 1(-75,-139.46) 2(-25,-139.46) 3(25,-139.46) 4(75,-139.46) 5(75,139.46) 6(25,139.46) 7(-25,139.46) 8(-75,139.46)
  silkscreen extent -111,-145 106,87
SOT-23-5 [mil]
  rect 50x20 smd paste+0 mask+4: 1(-65,100) 2(-65,63) 3(-65,25) 4(35,25) 5(35,100)
  silkscreen extent -65,1 18,135
TESTHOOK [mm]
  rect 2.3x2.3 hole 1.2 slot 1.8 at 0 deg paste+0 mask+0.102: 1(0,0)
  silkscreen extent -1.8,-1.8 1.8,1.8
USB-A-TH__USB-AF-90 [mm]
  round 1.7 hole 1.1 copper offset 0,0 paste+0 mask+0.051: 1(-3.5,1.355) 4(3.5,1.355)
  round 1.7 hole 1.1 paste+0 mask+0.051: 2(-1,1.355) 3(1,1.355)
  round 3.1 hole 2.1 paste+0 mask+0.051: SH1(7,-1.355) SH2(-7,-1.355)
  silkscreen extent -7.22,-11.51 7.22,2.49
USB-C-SMD_TYPEC-304-BCP16#1 [mil]
  oval 39.4x82.7 hole 23.6 slot 70.9 at 90 deg paste+0 mask+2: 13(-170.1,64.3) 14(170.1,64.3)
  oval 39.4x63 hole 23.6 slot 47.2 at 90 deg paste+0 mask+2: 15(-170.1,-100.3) 16(170.1,-100.3)
  rect 23.6x57.1 smd paste+0 mask+2: A1B12(-127,100.3) A4B9(-96.5,100.3) B1A12(126.8,100.3) B4A9(96.5,100.3)
  rect 11.8x57.1 smd paste+0 mask+2: A5(-49.2,100.3) A6(-9.8,100.3) A7(9.8,100.3) A8(49.2,100.3) B5(68.9,100.3) B6(29.5,100.3) B7(-29.5,100.3) B8(-68.9,100.3)
  Multi-Layer board cut-out: 117.3,29.6 123.29,30.97 128.09,34.8 130.75,40.33 130.75,46.47 128.09,52 123.29,55.83 117.3,57.2 117.3,57.2 111.31,55.83 106.51,52 103.85,46.47 103.85,40.33 106.51,34.8 111.31,30.97 117.3,29.6
  Multi-Layer board cut-out: -117.3,29.6 -111.31,30.97 -106.51,34.8 -103.85,40.33 -103.85,46.47 -106.51,52 -111.31,55.83 -117.3,57.2 -117.3,57.2 -123.29,55.83 -128.09,52 -130.75,46.47 -130.75,40.33 -128.09,34.8 -123.29,30.97 -117.3,29.6
  silkscreen extent -170,-200 170,120
USB-C-SMD_TYPEC-304-BCP16#2 [mil]
  oval 39.4x82.7 hole 23.6 slot 70.9 at 90 deg paste+0 mask+2: 13(-170.1,64.3) 14(170.1,64.3)
  oval 39.4x63 hole 23.6 slot 47.2 at 90 deg paste+0 mask+2: 15(-170.1,-100.3) 16(170.1,-100.3)
  rect 23.6x57.1 smd paste+0 mask+2: A1B12(-127,100.3) A4B9(-96.5,100.3) B1A12(126.8,100.3) B4A9(96.5,100.3)
  rect 11.8x57.1 smd paste+0 mask+2: A5(-49.2,100.3) A6(-9.8,100.3) A7(9.8,100.3) A8(49.2,100.3) B5(68.9,100.3) B6(29.5,100.3) B7(-29.5,100.3) B8(-68.9,100.3)
  Multi-Layer board cut-out: 103.5,43.4 104.87,37.41 108.7,32.61 114.23,29.95 120.37,29.95 125.9,32.61 129.73,37.41 131.1,43.4 131.1,43.4 129.73,49.39 125.9,54.19 120.37,56.85 114.23,56.85 108.7,54.19 104.87,49.39 103.5,43.4
  Multi-Layer board cut-out: -131.1,43.4 -129.73,37.41 -125.9,32.61 -120.37,29.95 -114.23,29.95 -108.7,32.61 -104.87,37.41 -103.5,43.4 -103.5,43.4 -104.87,49.39 -108.7,54.19 -114.23,56.85 -120.37,56.85 -125.9,54.19 -129.73,49.39 -131.1,43.4
  silkscreen extent -170,-200 170,120
"XTAL_SOP - FC-12M" [mm]
  rect 0.8x1.5 smd paste+0 mask+0.102: 1(0,0) 2(1.5,0)
  silkscreen extent -0.81,-0.99 2.29,0.94

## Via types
v1: diameter 19.68, hole 11.81, Top Layer to Bottom Layer, 621 vias
v2: diameter 19.69, hole 11.81, Top Layer to Bottom Layer, 42 vias
v3: diameter 19.7, hole 11.81, Top Layer to Bottom Layer, 26 vias
v4: diameter 23.62, hole 11.81, Top Layer to Bottom Layer, 17 vias
v5: diameter 27.56, hole 13.78, Top Layer to Bottom Layer, 15 vias
v6: diameter 24, hole 12, Top Layer to Bottom Layer, 7 vias
v7: diameter 27.56, hole 15.75, Top Layer to Bottom Layer, 2 vias

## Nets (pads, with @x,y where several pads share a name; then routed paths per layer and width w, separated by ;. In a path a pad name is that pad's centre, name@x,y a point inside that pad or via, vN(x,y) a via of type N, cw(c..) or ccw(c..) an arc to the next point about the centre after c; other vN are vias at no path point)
3V3: C20.2 CN2.1 CN7.1 D2.2 D4.1 D5.1 J4.2 J4.4 J8.1 JP3.1 R3.1 R4.2 R13.2 R14.2 R15.2 U8.8 | length 11353.6
  Top Layer w10: R3.1@14494.08,5259.56 14495.08,5258.56 R4.2@14620.08,5258.56
  Top Layer w15: v2(14764.58,5062.56) 14764.92,5062.22 R15.2@14843.69,5062.21
  Top Layer w20: v7(13264.34,3610.01) 13221.01,3653.34 13221.01,4929.24 13303.83,5012.05 D5.1@13303.83,5091.56 ; v2(13782.58,3570.57) 13782.58,3694.57 13820.58,3732.57 14008.58,3732.57 14051.58,3775.57 v2(14051.58,4190.56) ; R4.2@14620.08,5258.56 14620.58,5259.06 JP3.1@14620.58,5358.55 14620.58,5400.36 D2.2@14690.58,5470.36 ; v1(14773.58,3837.57) 14773.86,3837.28 v3(15343.7,3837.28) v1(15683.86,3837.28) 17499.28,3837.28 17552.58,3890.57 J8.1@17630.74,3890.57 ; R15.2@14843.69,5062.21 14845.08,5060.84 R13.2@14845.08,4890.56 ; v3(15223.58,4371.56) C20.2@15313.58,4371.56 15314.03,4371.1 U8.8@15314.03,4291.56 ; J4.2@15683.86,3566.56 15683.88,3611.86 15702.58,3630.57 15863.58,3630.57 15883.88,3610.26 J4.4@15883.86,3566.56
  Bottom Layer w15: JP3.1@14620.58,5358.55 14620.58,5206.56 v2(14764.58,5062.56) ; v1@15683.58,3837.57 v1(15683.86,3837.28)
  Bottom Layer w20: v7(13264.34,3610.01) 13303.8,3570.57 v2(13782.58,3570.57) D4.1@13782.58,3415.2 13782.58,3388.68 13737.92,3344.01 13737.92,3230.01 13715.34,3207.45 CN7.1@13715.34,3167.01 ; JP3.1@14620.58,5358.55 14138.58,5358.56 14051.58,5271.56 v2(14051.58,4190.56) 14290.2,4190.56 CN2.1@14290.92,4189.85 14365.65,4264.56 14708.58,4264.56 14773.58,4199.56 v1(14773.58,3837.57) ; v3(15223.58,4371.56) 15223.58,3957.57 v3@15343.58,3837.57 ; J4.2@15683.86,3566.56 v1(15683.86,3837.28)
5V: CN1.1 CN2.2 CN7.2 D1.2 D3.1 F1.1 J4.5 J7.2 | length 10223.9
  Top Layer w30: v7(13672.58,3240.57) 13672.58,3694.57 13750.58,3772.57 13962.58,3772.57 14000.58,3810.57 14000.58,5470.56 14044.89,5514.88 F1.1@14096.38,5514.88 ; 14000.58,4238.98 14003.3,4238.98 14036.13,4271.81 ; 14000.58,4305.48 14002.46,4305.48 14036.13,4271.81 ; CN2.2@14390.92,4189.85 14390.92,4250.22 14369.33,4271.81 14036.13,4271.81 ; J7.2@17098.88,4667.16 17133.97,4667.16 17285.58,4515.56 D1.2@17342.58,4515.56
  Bottom Layer w15: D3.1@13676.62,3321.82 13676.58,3240.57 13664.58,3228.57 13664.58,3117.78 CN7.2@13715.34,3067.01 ; J4.5@15982.88,3566.56 15982.88,3499.26 16034.07,3448.07 16033.55,3116.86 16031.05,3114.36 ; 16032.05,3110.43 16032.05,3114.36
  Bottom Layer w30: CN2.2@14390.92,4189.85 14653.3,4189.85 14720.58,4122.56 14720.58,3185.66 14791.89,3114.36 16031.05,3114.36 16032.05,3114.36 16960.38,3114.36 17205.58,3359.57 17205.58,4608.84 ; J7.2@17098.88,4667.16 17204.25,4667.16 ; 17204.25,4610.16 17205.58,4608.84 ; 17204.25,4664.16 17205.58,4665.49 ; 17205.58,4665.84 17205.58,4665.49 ; 17239.58,4698.49 17239.58,4699.49 ; 17310.77,5222.76 CN1.1@17413.22,5222.76 ; 17310.77,5223.76 17239.58,5152.56 17239.58,4699.49 ; 17205.58,4608.84 17205.58,4665.49 ; 17205.58,4665.49 17239.58,4699.49
$1N307: J9.2 U6.44 | length 154.6
  Top Layer w6: U6.44@13659.15,4535.23 13730.56,4535.23 J9.2@13789.34,4594.02
$1N334: LD4.1 RP1.5 | length 138.2
  Top Layer w6: LD4.1@13742.62,5042.36 13785.37,5042.36 v5(13786.58,5043.56)
  Bottom Layer w6: RP1.5@13713.41,4993.86 13736.88,4993.86 v5(13786.58,5043.56)
$1N335: LD3.1 RP1.6 | length 123.1
  Top Layer w6: LD3.1@13742.62,4972.76 13785.38,4972.76 v5(13786.58,4971.56)
  Bottom Layer w6: RP1.6@13713.41,4958.44 13773.44,4958.44 v5(13786.58,4971.56)
$1N336: LD2.1 RP1.7 | length 125.3
  Top Layer w6: LD2.1@13742.62,4903.16 13786.17,4903.16 v5(13786.58,4903.56)
  Bottom Layer w6: RP1.7@13713.41,4922.99 13767.15,4922.99 v5(13786.58,4903.56)
$1N337: LD1.1 RP1.8 | length 147.5
  Top Layer w6: LD1.1@13742.62,4833.56 v5(13790.58,4833.56)
  Bottom Layer w6: RP1.8@13713.41,4887.56 13736.58,4887.56 v5(13790.58,4833.56)
$1N361: C15.1 C16.1 C18.1 C19.1 F2.2 U5.1 U5.3 U7.1 U7.3 | length 730.4
  Top Layer w20: U5.3@13320.14,5405.9 13320.15,5484.86 C18.1@13321.15,5485.86 ; U5.1@13395.14,5405.9 C19.1@13395.15,5485.86 ; U7.3@13689.34,5407.9 C15.1@13689.34,5486.07 ; U7.1@13764.34,5407.9 C16.1@13764.34,5487.9
  Top Layer w30: C18.1@13321.15,5485.86 C19.1@13395.15,5485.86 ; F2.2@13617.56,5487.94 13689.58,5487.94 C16.1@13764.31,5487.94
  Bottom Layer w30: v5(13427.14,5405.91) 13616.74,5405.91 v5(13617.84,5407.02)
$1N396: R50.1 R51.1 U5.4 | length 160.1
  Top Layer w25: R51.1@13254.58,5231.06 13332.58,5231.06 R50.1@13335.08,5233.56 13320.15,5248.49 U5.4@13320.14,5305.9
$1N467: R43.1 R49.1 U7.4 | length 163.5
  Top Layer w20: R49.1@13616.92,5236.02 R43.1@13702.92,5236.02 13702.92,5267.02 13689.34,5280.6 U7.4@13689.34,5307.9
$2N290: C3.1 D2.1 R1.2 U2.5 | length 294.6
  Top Layer w20: U2.5@14417.58,5577.53 14513.92,5577.53 R1.2@14518.58,5572.87 C3.1@14590.58,5572.87 14638.07,5620.36 D2.1@14690.58,5620.36
$2N291: R1.1 R2.2 U2.4 | length 180.7
  Top Layer w20: U2.4@14417.58,5502.53 14462.55,5502.53 14477.89,5517.88 R1.1@14518.58,5517.87 R2.2@14518.08,5444.56
$2N326: LED1.1 R3.2 | length 110.5
  Top Layer w10: LED1.1@14328.62,5259.36 14328.83,5259.56 R3.2@14439.08,5259.56
$2N337: C1.1 C2.1 F1.2 U2.1 U2.3 | length 370.1
  Top Layer w6: U2.3@14317.58,5502.53 14346.55,5502.53 14360.58,5516.56 14360.58,5565.56 14348.6,5577.53 U2.1@14317.58,5577.53
  Top Layer w20: F1.2@14096.38,5575.88 14099.38,5572.88 C1.1@14172.58,5572.87 C2.1@14232.58,5572.87 14237.24,5577.53 U2.1@14317.58,5577.53
$2N360: B2.3 B2.4 R5.2 R7.1 | length 593.1
  Top Layer w10: B2.4@14883.61,3367.74 14886.02,3370.14 15196.06,3370.14 15246.16,3370.14 15270.58,3394.57 15270.58,3471.68 15273.45,3474.57 15269.08,3478.95 R5.2@15269.08,3530.57 R7.1@15269.08,3586.57
$2N488: LED3.1 R14.1 | length 90.1
  Top Layer w10: R14.1@14898.69,4976.21 14899.25,4976.77 LED3.1@14988.53,4976.77
$2N489: LED2.1 R13.1 | length 88.5
  Top Layer w10: R13.1@14900.08,4890.56 14900.3,4890.77 LED2.1@14988.53,4890.77
$2N490: LED4.1 R15.1 | length 90.4
  Top Layer w10: R15.1@14898.69,5062.21 14900.14,5060.77 LED4.1@14988.53,5060.77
